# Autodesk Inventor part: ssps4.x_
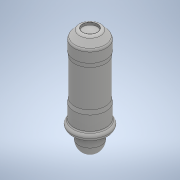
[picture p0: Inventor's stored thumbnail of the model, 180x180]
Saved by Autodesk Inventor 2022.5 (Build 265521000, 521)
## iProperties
Created: 2018-04
Part Number: ssps4.x_
Material: 一般
Document SubType Name: Modeling
Designer: imaocorp
Density: 1 g/cm^3
Appearance: 既定
Sending System: SOLIDWORKS 2016-2016286
MC: AMD64
MC_MODEL: AMD64 Family 21 Model 2 Stepping 0, AuthenticAMD
OS: Windows_NT
FRU: Parasolid Version 28.0, build 224,  7-29-2016
FORMAT: text
GUISE: transmit
KEY: ssps4
FILE: ssps4.x_t
DATE: Wed Apr 25 10:16:00 2018
Author: imaocorp
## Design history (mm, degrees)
feature "Base1"
node "ソリッド1"
